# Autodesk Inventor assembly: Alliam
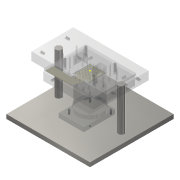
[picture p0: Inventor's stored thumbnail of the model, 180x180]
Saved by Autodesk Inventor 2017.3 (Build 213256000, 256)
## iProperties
Part Number: Alliam
Material: 一般
Document SubType Name: Assembly
Designer: kyushu-hep
Author: kyushu-hep
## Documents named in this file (8)
- E:\PixelAssembly\FlexAssembly3\Alliam.iam
- E:\PixelAssembly\FlexAssembly3\FlexBase.ipt
- E:\PixelAssembly\FlexAssembly3\ModuleBase.ipt
- E:\PixelAssembly\FlexAssembly3\Module.ipt
- E:\PixelAssembly\FlexAssembly3\FPC2.ipt
- E:\PixelAssembly\FlexAssembly3\base1.ipt
- E:\PixelAssembly\FlexAssembly3\ClearBoard.ipt
- E:\PixelAssembly\FlexAssembly3\Stages.ipt
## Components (7 placed, 7 different names)
1. FlexBase:1 — メイト:18, メイト:19, メイト:20, メイト:21, メイト:22, メイト:32, メイト:33
2. base1:1 — メイト:13, メイト:14, メイト:26, メイト:27, メイト:28, メイト:32, メイト:33
3. FPC2:1 — メイト:21, メイト:22, メイト:23
4. ModuleBase:1 — メイト:15, メイト:16, メイト:17, メイト:31
5. Module:1 — メイト:15, メイト:16, メイト:17
6. ClearBoard:1 — メイト:18, メイト:19, メイト:20, メイト:23
7. Stages:1 — メイト:26, メイト:27, メイト:28, メイト:31
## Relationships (17: Mate 17)
- メイト:13 [Mate]: base1:1
- メイト:14 [Mate]: base1:1
- メイト:15 [Mate]: ModuleBase:1 ↔ Module:1
- メイト:16 [Mate]: ModuleBase:1 ↔ Module:1
- メイト:17 [Mate]: ModuleBase:1 ↔ Module:1
- メイト:18 [Mate]: FlexBase:1 ↔ ClearBoard:1
- メイト:19 [Mate]: FlexBase:1 ↔ ClearBoard:1
- メイト:20 [Mate]: FlexBase:1 ↔ ClearBoard:1
- メイト:21 [Mate]: FlexBase:1 ↔ FPC2:1
- メイト:22 [Mate]: FlexBase:1 ↔ FPC2:1
- メイト:23 [Mate]: FPC2:1 ↔ ClearBoard:1
- メイト:26 [Mate]: base1:1 ↔ Stages:1
- メイト:27 [Mate]: base1:1 ↔ Stages:1
- メイト:28 [Mate]: base1:1 ↔ Stages:1
- メイト:31 [Mate]: ModuleBase:1 ↔ Stages:1
- メイト:32 [Mate]: FlexBase:1 ↔ base1:1
- メイト:33 [Mate]: FlexBase:1 ↔ base1:1
